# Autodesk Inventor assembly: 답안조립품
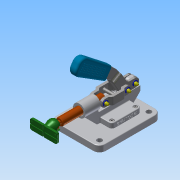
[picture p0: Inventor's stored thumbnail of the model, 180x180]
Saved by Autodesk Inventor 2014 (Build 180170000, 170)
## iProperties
Created: 2017-10
Part Number: 답안조립품
Document SubType Name: Assembly
Designer: user
Mass: 534.087 g
Surface Area: 580.4 cm^2
Volume: 155.316 cm^3
Density: 3.43872 g/cm^3
Author: user
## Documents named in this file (12)
- C:\Users\user\Desktop\새 폴더\답안조립품.iam
- C:\Users\user\Desktop\새 폴더\플레이트.ipt
- C:\Users\user\Desktop\새 폴더\본체.ipt
- C:\Users\user\Desktop\새 폴더\레버.ipt
- C:\Users\user\Desktop\새 폴더\그립 커버.ipt
- C:\Users\user\Desktop\새 폴더\축.ipt
- C:\Users\user\Desktop\새 폴더\연결대.ipt
- C:\Users\user\Desktop\새 폴더\클램프.ipt
- C:\Users\user\Desktop\새 폴더\클레비스 핀 5x18.ipt
- C:\Users\user\Desktop\새 폴더\E-링.ipt
- C:\Users\user\Desktop\새 폴더\클레비스 핀 5x26.ipt
- C:\Users\user\Desktop\새 폴더\볼트 M3x10.ipt
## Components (5 placed, 3 different names)
1. 플레이트:1 — 각도:1, 각도:2, 각도:4, 각도:5, 각도:6
2. 그립 커버:1
3. E-링:1 — 각도:4
4. E-링:2 — 각도:5
5. E-링:3 — 각도:6
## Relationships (5: Angle 5)
- 각도:1 [Angle]: 플레이트:1
- 각도:2 [Angle]: 플레이트:1
- 각도:4 [Angle]: 플레이트:1 ↔ E-링:1
- 각도:5 [Angle]: 플레이트:1 ↔ E-링:2
- 각도:6 [Angle]: 플레이트:1 ↔ E-링:3
